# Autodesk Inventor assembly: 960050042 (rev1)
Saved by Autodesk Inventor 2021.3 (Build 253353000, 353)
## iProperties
Created: 2023-03
Part Number: 960050042 (rev1)
Document SubType Name: Assembly
Designer: AdminForWorker
Title: 960050042 (rev1) v2
Author: AdminForWorker
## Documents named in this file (2)
- z:\worker\convert-fusion-r08-cosv3\tmp\job-1\3553\output\files\82b4d9ad-b575-4129-b9ca-4964d6b72adf\960050042 (rev1) v2_6.iam
- z:\worker\convert-fusion-r08-cosv3\tmp\job-1\3553\output\files\82b4d9ad-b575-4129-b9ca-4964d6b72adf\960050042 (rev1).ipt
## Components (1 placed, 1 different names)
1. 960050042 (rev1):1
